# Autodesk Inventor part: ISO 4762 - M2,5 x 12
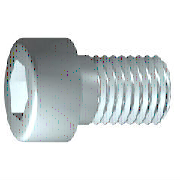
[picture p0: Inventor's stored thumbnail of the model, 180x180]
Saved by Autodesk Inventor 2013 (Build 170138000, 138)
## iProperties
Created: 2012-02
Part Number: ISO 4762 - M2,5 x 12
Material: Edelstahl, 440C
Description: Innensechskantschraube
Document SubType Name: Modeling
Standard: ISO 4762
Designer: rYan
Standard Revision: 1998
Standards Organization: DIN
Language: de-DE
Size Designation: M2,5 x 12
Categories: <MemberInstance><Categories><Category DisplayName="Verbindungselemente" InternalName="e4da775c-781d-43d5-af7c-5136215cf5a6" Mnemonic="FSTN"><Category DisplayNam
Density: 7.75 g/cm^3
IsCustomPart: 0
Author: rYan
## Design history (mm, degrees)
sketch "Skizze1"
  geometry: L1 (-0.733, 0)-(12, 0); L2 (12, 0)-(12, 1.25); L3 (12, 1.25)-(1.125, 1.25); L4 (1.125, 1.25)-(0.849, 1.25); L5 (0.849, 1.25)-(0, 1.25); L6 (0, 1.25)-(0, 2.25); L7 (0, 2.25)-(-2.5, 2.25); L8 (-2.5, 2.25)-(-2.5, 1.155); L9 (-2.5, 1.155)-(-1.4, 1.155); L10 (-1.4, 1.155)-(-0.733, 0); L11 (-5.4, 0)-(14.9, 0) reference; L12 (0, -0.45)-(0, 2.7) reference; L13 (1.125, 1.25)-(0, 1.25)
  constraints: 22 end point, 6 parallel, 2 collinear, 2 perpendicular, 1 horizontal, 1 point on line
  dimensions: "d1" = 10.875 distance from line of L3.end L2 (= GEL); "d2" = 0.27615 distance of L4.end L3.end (computed from GAL); "d3" = 2.5 distance between parallel lines of L8 L6 (= KOH); "d4" = 1.1 distance of L8.end L9.end (= INTI); "d5" = 60 deg angle of L10 L1; "d6" = 2.5 diameter of L3 L1 (= GD); "d7" = 2.5 diameter of L5 L1 (= BDM); "d8" = 2.3094 diameter of L9 L1 (= 1.1547 x SW); "d9" = 4.5 diameter of L7 L1 (= KOD); "d26" = 12 distance between parallel lines of L12 L2 (= NLG)
revolve "Körper" sketch "Skizze1" stored, may be unused: angle "d10" = 90 deg
sketch "Skizze2"
  geometry: L1 (0, -3.15)-(0, 3.15) reference; L2 (-3.15, 0)-(3.15, 0) reference; L3 (1.155, 0)-(0.577, -1); L4 (0.577, -1)-(-0.577, -1); L5 (-0.577, -1)-(-1.155, 0); L6 (-1.155, 0)-(-0.577, 1); L7 (-0.577, 1)-(0.577, 1); L8 (0.577, 1)-(1.155, 0); 2 further points
  constraints: 12 end point, 1 coincident, 1 horizontal alignment, 1 point on line, 12 other
extrude "Loch" join sketch "Skizze2" stored distance "d11" = 10; taper "d12" = 0 deg
workplane "Work Plane1"
fillet "Fillet2" dims "d30" = 0.1 (= R)
body "Solid1"
fillet "Rundung1" dims "d17" = 0.25 (= RR)
feature "Gewinde" dims "d13" = 10.875 (= GEL), "d14" = 0
chamfer "Fase1" distance "d15" = 0.27605 (= -0.5 x SPD + 0.5 x GD); stored, may be unused: second distance "d16" = 0.27605 (= GUL), angle "d27" = 45 deg
other parameters: "GD" = 2.5 [user parameter; used in 2 equation terms], "NLG" = 12 [user parameter; used in 1 equation term], "GEL" = 10.875 [user parameter; used in 2 equation terms], "KOD" = 4.5 [user parameter; used in 1 equation term], "KOH" = 2.5 [user parameter; used in 1 equation term], "INTI" = 1.1 [user parameter; used in 1 equation term], "GAL" = 0.27605 (= 0.61345 x PTC) [user parameter; used in 1 equation term], "GUL" = 0.27605 (= 0.61345 x PTC) [user parameter; used in 1 equation term], "BDM" = 2.5 (= NND) [user parameter; used in 1 equation term], "SW" = 2 [user parameter; used in 2 equation terms], "RR" = 0.25 [user parameter; used in 1 equation term], "SPD" = 1.94789 (= NND - 1.2269 x PTC) [user parameter; used in 1 equation term], "d19" = 0, "d28" = 0, "d29" = 0, "R" = 0.1 [user parameter; used in 1 equation term], "TOA" = 30 deg [user parameter], "GD1" = 1.94789 (= THREADDIA - 1.2269 x PTC) [user parameter], "THREADDIA" = 2.5 [user parameter; used in 1 equation term], "FAWI" = 45 deg [user parameter], "TPU" = 22.22222 (computed from PTC) [user parameter], "PTC" = 0.45 [user parameter; used in 5 equation terms], "NND" = 2.5 [user parameter; used in 2 equation terms], "E0" = 2.31 (= 1.155 x SW) [user parameter]
